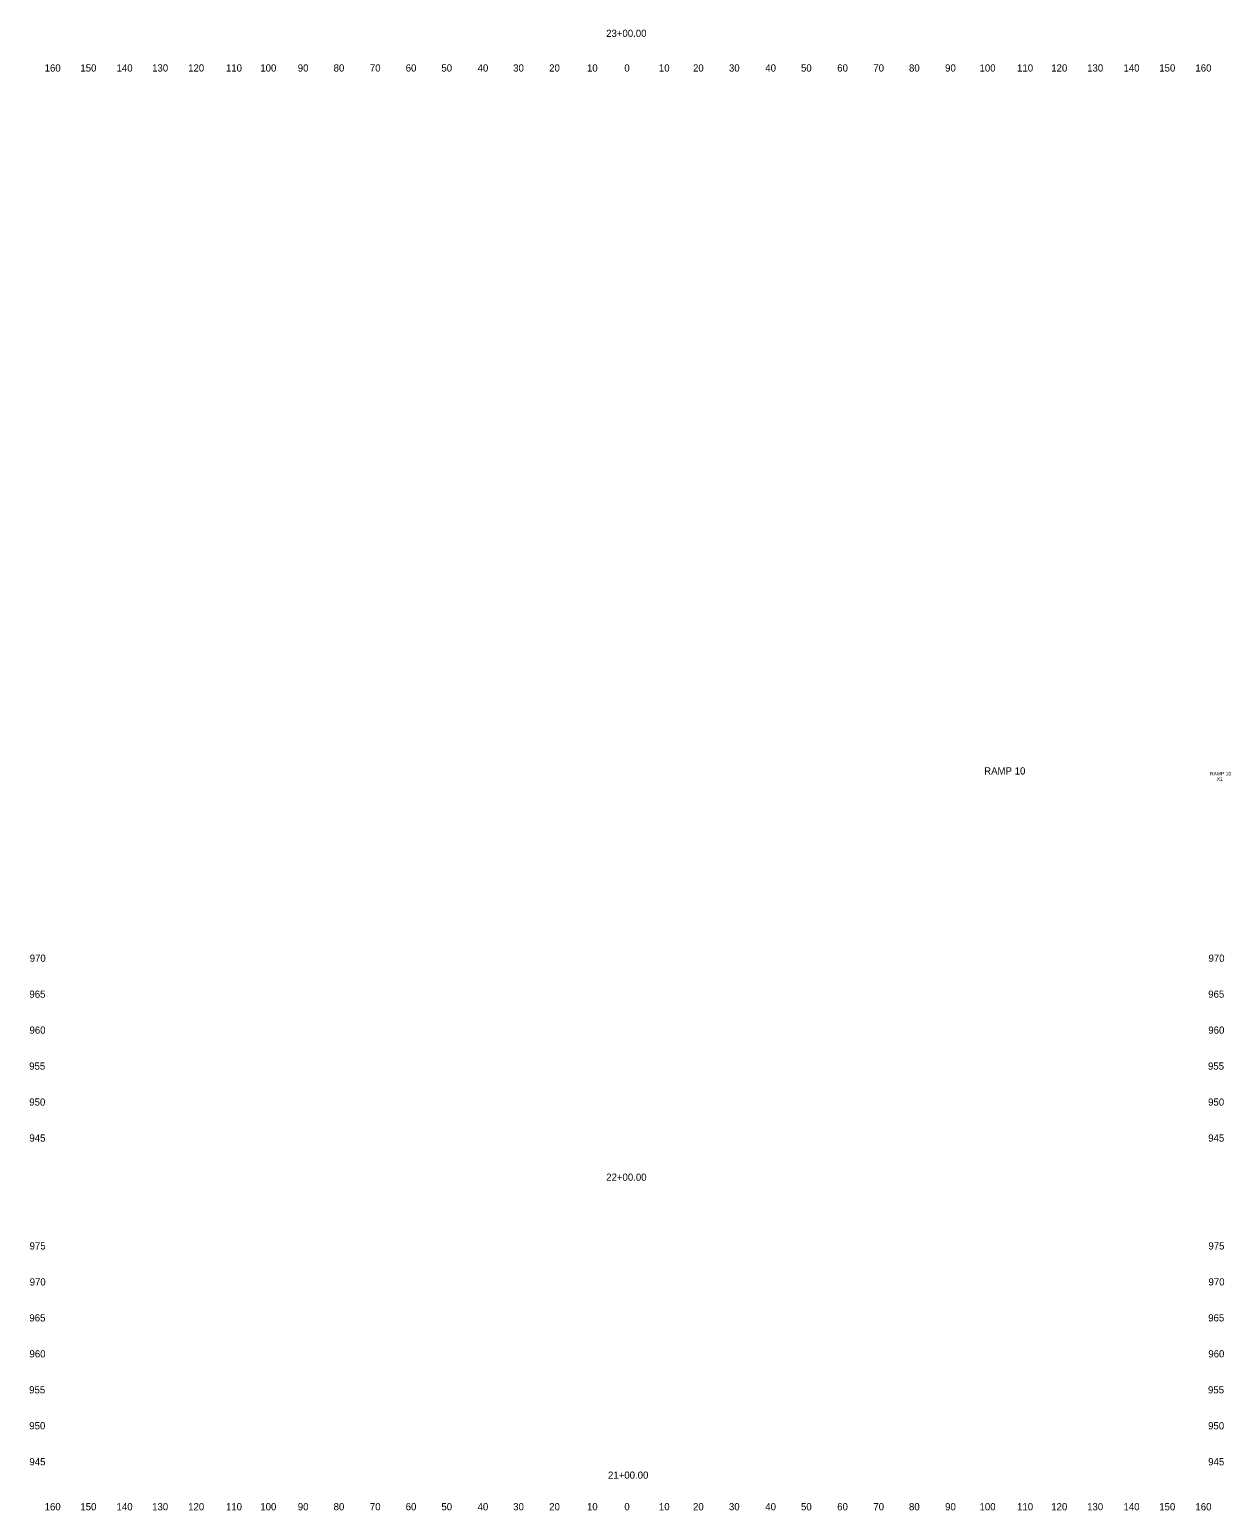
# Model space of a CAD drawing. Extents: x 4994 to 5328, y 4997 to 8404.
# Drawn here: x 4993.9 to 5327.8, y 4997.5 to 5409.2 of the extents above; entities that cross this region are included whole.
import ezdxf

# ---------------------------------------------------------------- set-up
doc = ezdxf.new("R2010")
doc.units = 0
for name, color, linetype in [('RD_SHT_ID', 7, 'Continuous'), ('RD_XS_TX_Offset', 7, 'Continuous'), ('RD_XS_TX_Station', 7, 'Continuous')]:
    doc.layers.add(name, color=color, linetype=linetype)

msp = doc.modelspace()

# ---------------------------------------------------------------- texts
at = {"layer": 'RD_SHT_ID'}
for s, height, p in [('RAMP 10', 2, (5259.37, 5202.06)), ('RAMP 10', 1, (5322.16, 5201.8)), ('X1', 1, (5324.02, 5200.3))]:
    msp.add_text(s, height=height, dxfattribs=at).set_placement(p)
at = {"layer": 'RD_XS_TX_Offset'}
for s, p in [('160', (4998.1, 5397.5)), ('150', (5008.04, 5397.5)), ('140', (5018.1, 5397.5)), ('130', (5027.99, 5397.5)), ('120', (5038.01, 5397.5)), ('110', (5048.51, 5397.5)), ('100', (5058.07, 5397.5)), ('90', (5068.5, 5397.5)), ('80', (5078.46, 5397.5)), ('70', (5088.54, 5397.5)), ('60', (5098.5, 5397.5)), ('50', (5108.43, 5397.5)), ('40', (5118.5, 5397.5)), ('30', (5128.39, 5397.5)), ('20', (5138.4, 5397.5)), ('10', (5148.91, 5397.5)), ('0', (5159.3, 5397.5)), ('0', (5159.3, 5397.5)), ('10', (5168.91, 5397.5)), ('20', (5178.4, 5397.5)), ('30', (5188.39, 5397.5)), ('40', (5198.5, 5397.5)), ('50', (5208.43, 5397.5)), ('60', (5218.5, 5397.5)), ('70', (5228.54, 5397.5)), ('80', (5238.46, 5397.5)), ('90', (5248.5, 5397.5)), ('100', (5258.07, 5397.5)), ('110', (5268.51, 5397.5)), ('120', (5278.01, 5397.5)), ('130', (5287.99, 5397.5)), ('140', (5298.1, 5397.5)), ('150', (5308.04, 5397.5)), ('160', (5318.1, 5397.5)), ('970', (4993.94, 5150)), ('970', (5321.74, 5150)), ('965', (4993.86, 5140)), ('965', (5321.66, 5140)), ('960', (4993.89, 5130)), ('960', (5321.69, 5130)), ('955', (4993.8, 5120)), ('955', (5321.6, 5120)), ('950', (4993.83, 5110)), ('950', (5321.63, 5110)), ('945', (4993.86, 5100)), ('945', (5321.66, 5100)), ('975', (4993.91, 5070)), ('975', (5321.71, 5070)), ('970', (4993.94, 5060)), ('970', (5321.74, 5060)), ('965', (4993.86, 5050)), ('965', (5321.66, 5050)), ('960', (4993.89, 5040)), ('960', (5321.69, 5040)), ('955', (4993.8, 5030)), ('955', (5321.6, 5030)), ('950', (4993.83, 5020)), ('950', (5321.63, 5020)), ('945', (4993.86, 5010)), ('945', (5321.66, 5010)), ('160', (4998.1, 4997.5)), ('150', (5008.04, 4997.5)), ('140', (5018.1, 4997.5)), ('130', (5027.99, 4997.5)), ('120', (5038.01, 4997.5)), ('110', (5048.51, 4997.5)), ('100', (5058.07, 4997.5)), ('90', (5068.5, 4997.5)), ('80', (5078.46, 4997.5)), ('70', (5088.54, 4997.5)), ('60', (5098.5, 4997.5)), ('50', (5108.43, 4997.5)), ('40', (5118.5, 4997.5)), ('30', (5128.39, 4997.5)), ('20', (5138.4, 4997.5)), ('10', (5148.91, 4997.5)), ('0', (5159.3, 4997.5)), ('0', (5159.3, 4997.5)), ('10', (5168.91, 4997.5)), ('20', (5178.4, 4997.5)), ('30', (5188.39, 4997.5)), ('40', (5198.5, 4997.5)), ('50', (5208.43, 4997.5)), ('60', (5218.5, 4997.5)), ('70', (5228.54, 4997.5)), ('80', (5238.46, 4997.5)), ('90', (5248.5, 4997.5)), ('100', (5258.07, 4997.5)), ('110', (5268.51, 4997.5)), ('120', (5278.01, 4997.5)), ('130', (5287.99, 4997.5)), ('140', (5298.1, 4997.5)), ('150', (5308.04, 4997.5)), ('160', (5318.1, 4997.5))]:
    msp.add_text(s, height=2, dxfattribs=at).set_placement(p)
at = {"layer": 'RD_XS_TX_Station'}
for s, p in [('23+00.00', (5154.24, 5407.13)), ('22+00.00', (5154.26, 5089.11)), ('21+00.00', (5154.76, 5006.27))]:
    msp.add_text(s, height=2, dxfattribs=at).set_placement(p)

doc.saveas('drawing.dxf')
